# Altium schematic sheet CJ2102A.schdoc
size 127 x 101 mm
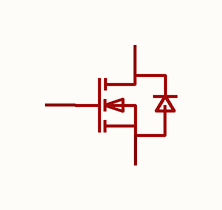
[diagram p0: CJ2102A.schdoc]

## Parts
Q?  cj2102a  [SOT-323-3_L2.0-W1.3-P1.30-LS2.3-BR]  (value not drawn)

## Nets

Not connected (* = marked no-connect by the designer): Q? 1(G) 2(S) 3(D)

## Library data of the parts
Q? = cj2102a: 数量:1个N沟道;漏源电压(Vdss):20V;连续漏极电流(Id):2.1A;导通电阻(RDS(on)):115mΩ@2.5V;耗散功率(Pd):200mW;阈值电压(Vgs(th)):1.2V;; Manufacturer: CJ(江苏长电/长晶); AddInBom: yes; ModelId: 79e13e6d92094c298870c4de3aae48a2; ModelTransform: 90.551,78.74,0,0,0,0,0,0,0; Number: 1个N沟道; Drain to Source Voltage: 20V; Current - Continuous Drain(Id): 2.1A; Pd - Power Dissipation: 200mW; Gate Threshold Voltage (Vgs(th)): 1.2V; Gate Charge(Qg): 10nC@4.5V; Input Capacitance(Ciss): 330pF; Reverse Transfer Capacitance (Crss@Vds): 50pF; Type: N沟道; Output Capacitance(Coss): 60pF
